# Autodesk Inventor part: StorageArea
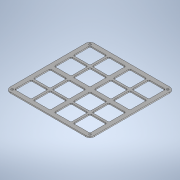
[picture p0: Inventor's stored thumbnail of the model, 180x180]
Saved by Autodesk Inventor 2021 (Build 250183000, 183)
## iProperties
Created: 2026-10
Part Number: StorageArea
Material: Generic
Document SubType Name: Modeling
Designer: hp
Density: 1 g/cm^3
Appearance: Default
Author: hp
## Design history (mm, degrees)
sketch "Sketch1"
  geometry: L1 (384.652, 11.52)-(464.652, 11.52); L2 (464.652, 11.52)-(464.652, 91.52); L3 (464.652, 91.52)-(384.652, 91.52); L4 (384.652, 91.52)-(384.652, 11.52); L5 (384.652, -78.48)-(464.652, -78.48); L6 (464.652, -78.48)-(464.652, 1.52); L7 (464.652, 1.52)-(384.652, 1.52); L8 (384.652, 1.52)-(384.652, -78.48); L9 (474.652, 11.52)-(554.652, 11.52); L10 (554.652, 11.52)-(554.652, 91.52); L11 (554.652, 91.52)-(474.652, 91.52); L12 (474.652, 91.52)-(474.652, 11.52); L13 (474.652, -78.48)-(554.652, -78.48); L14 (554.652, -78.48)-(554.652, 1.52); L15 (554.652, 1.52)-(474.652, 1.52); L16 (474.652, 1.52)-(474.652, -78.48); L17 (474.652, -268.48)-(554.652, -268.48); L18 (554.652, -268.48)-(554.652, -188.48); L19 (384.652, -178.48)-(464.652, -178.48); L20 (474.652, -188.48)-(474.652, -268.48); L21 (464.652, -268.48)-(464.652, -188.48); L22 (464.652, -188.48)-(384.652, -188.48); L23 (384.652, -268.48)-(464.652, -268.48); L24 (384.652, -188.48)-(384.652, -268.48); L25 (384.652, -98.48)-(384.652, -178.48); L26 (464.652, -98.48)-(384.652, -98.48); L27 (464.652, -178.48)-(464.652, -98.48); L28 (554.652, -188.48)-(474.652, -188.48); L29 (474.652, -178.48)-(554.652, -178.48); L30 (474.652, -98.48)-(474.652, -178.48); L31 (554.652, -98.48)-(474.652, -98.48); L32 (554.652, -178.48)-(554.652, -98.48); L33 (664.652, -78.48)-(744.652, -78.48); L34 (744.652, -78.48)-(744.652, 1.52); L35 (574.652, 11.52)-(654.652, 11.52); L36 (664.652, 1.52)-(664.652, -78.48); L37 (654.652, -78.48)-(654.652, 1.52); L38 (654.652, 1.52)-(574.652, 1.52); L39 (574.652, -78.48)-(654.652, -78.48); L40 (574.652, 1.52)-(574.652, -78.48); L41 (574.652, 91.52)-(574.652, 11.52); L42 (654.652, 91.52)-(574.652, 91.52); L43 (654.652, 11.52)-(654.652, 91.52); L44 (744.652, 1.52)-(664.652, 1.52); L45 (664.652, 11.52)-(744.652, 11.52); L46 (664.652, 91.52)-(664.652, 11.52); L47 (744.652, 91.52)-(664.652, 91.52); L48 (744.652, 11.52)-(744.652, 91.52); L49 (664.652, -268.48)-(744.652, -268.48); L50 (744.652, -268.48)-(744.652, -188.48); L51 (574.652, -178.48)-(654.652, -178.48); L52 (664.652, -188.48)-(664.652, -268.48); L53 (654.652, -268.48)-(654.652, -188.48); L54 (654.652, -188.48)-(574.652, -188.48); L55 (574.652, -268.48)-(654.652, -268.48); L56 (574.652, -188.48)-(574.652, -268.48); L57 (574.652, -98.48)-(574.652, -178.48); L58 (654.652, -98.48)-(574.652, -98.48); L59 (654.652, -178.48)-(654.652, -98.48); L60 (744.652, -188.48)-(664.652, -188.48); L61 (664.652, -178.48)-(744.652, -178.48); L62 (664.652, -98.48)-(664.652, -178.48); L63 (744.652, -98.48)-(664.652, -98.48); L64 (744.652, -178.48)-(744.652, -98.48)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; C1 r 5 at (379.652, 96.52); C2 r 5 at (749.652, 96.52); C3 r 5 at (379.652, -273.48); C4 r 5 at (749.652, -273.48)
  constraints: 140 end point, 4 centre point, 4 collinear, 4 horizontal, 4 midpoint, 4 parallel, 3 symmetric about line, 2 perpendicular, 2 vertical, 119 other
  dimensions: "d6" = 80 distance of L3.end L2.end; "d7" = 80 distance of L2.end L1.end; "d28" = 90 distance of L1.start L5.start; "d31" = 90 distance of L1.start L9.start; "d36" = 190 distance of L1.end L19.end; "d39" = 190 distance of L1.end L35.end; "d42" = 20 distance between parallel lines of L24 L68; "d43" = 20 distance between parallel lines of L17 L67; "d44" = 20 distance between parallel lines of L64 L66; "d45" = 20 distance between parallel lines of L11 L65; "d47" = 10 diameter of C1; "d48" = 15 distance from line of L65 C1.centre (= d49); "d49" = 15 distance from line of L68 C1.centre
extrude "Extrusion1" new body sketch "Sketch1" distance "d20" = 5; taper "d21" = 0 deg
fillet "Fillet1" dims "d24" = 5
fillet "Fillet2" dims "d46" = 20
extrude "Extrusion2" cut sketch "Sketch1" distance "d51" = 10; taper "d52" = 0 deg
body "Solid1"
